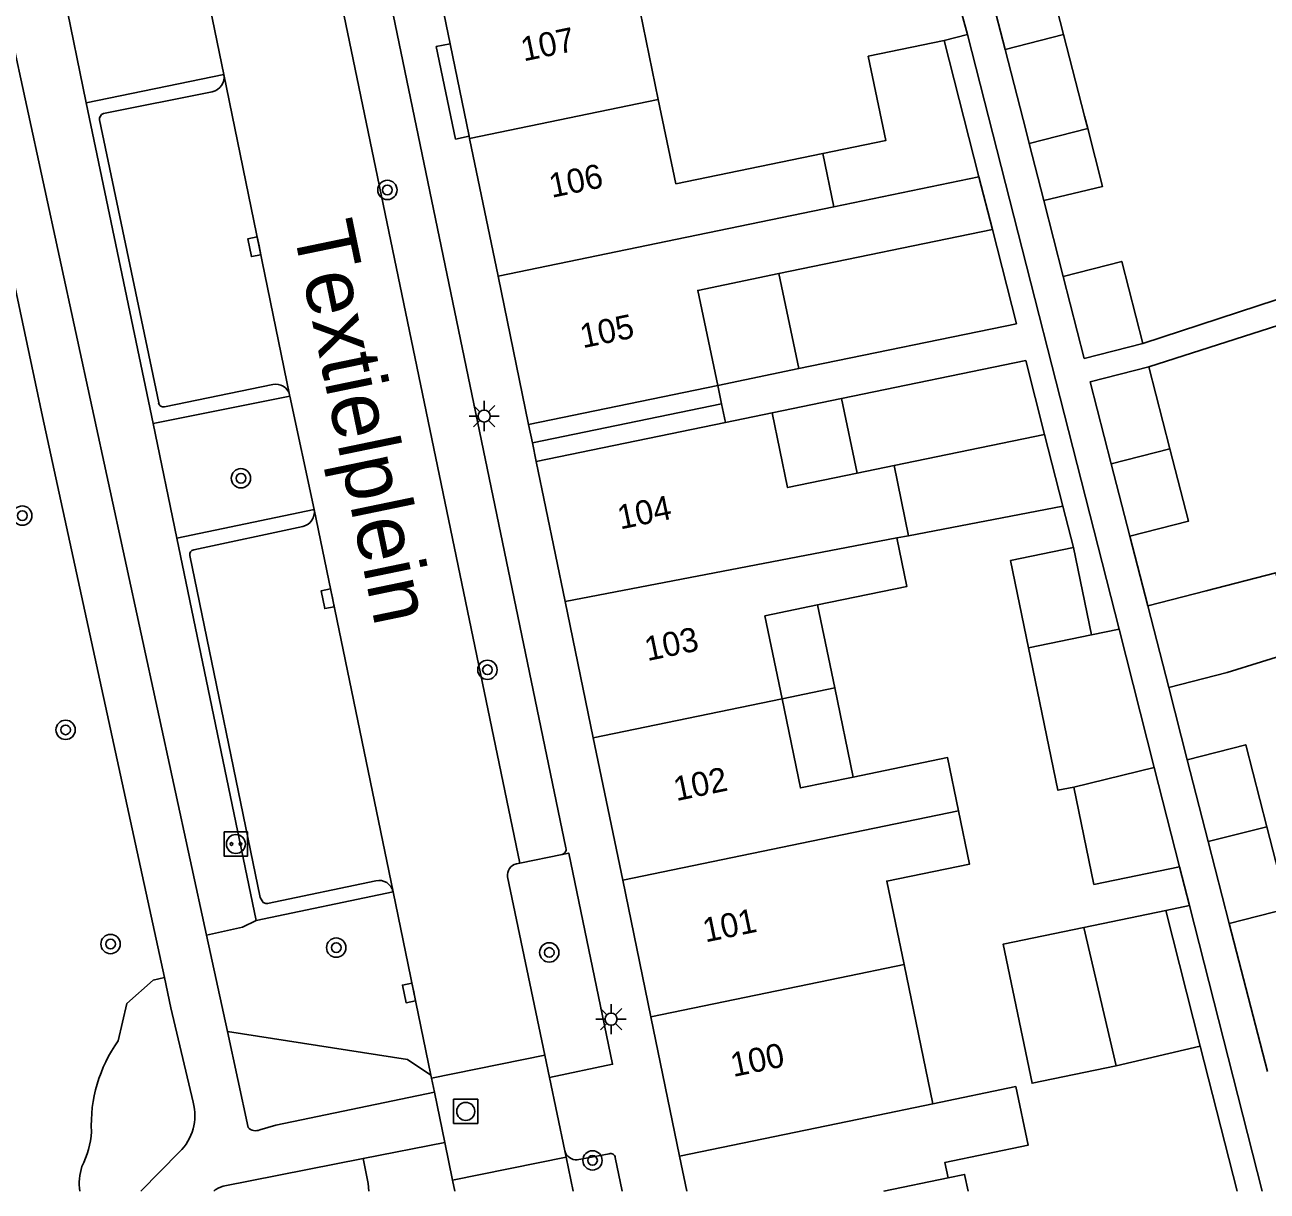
# Model space of a CAD drawing. Extents: x 132999 to 136000, y 398499 to 400501.
# Drawn here: x 133326.1 to 133377.5, y 398500 to 398548.3 of the extents above; entities that cross this region are included whole.
import ezdxf

# ---------------------------------------------------------------- set-up
doc = ezdxf.new("R2010")
doc.units = 0
for name, color, linetype in [('gg-afsc-erfafscheiding', 7, 'Continuous'), ('gg-anno-huisnummerreeks BGT', 7, 'Continuous'), ('gg-anno-openbare ruimte label', 7, 'Continuous'), ('gg-bbg-gedigitaliseerde bebouwing', 7, 'Continuous'), ('gg-bbg-gedigitaliseerde bijgebouw', 7, 'Continuous'), ('gg-bbg-hoofdgebouw', 7, 'Continuous'), ('gg-bbg-luifel en loopbrug', 7, 'Continuous'), ('gg-bbg-onder overbouw', 7, 'Continuous'), ('gg-bbg-pand overbouw', 7, 'Continuous'), ('gg-bbg-tussenscheiding', 7, 'Continuous'), ('gg-bbg-tussenscheiding niveau 01', 7, 'Continuous'), ('gg-knt-verharding', 7, 'Continuous'), ('gg-knt-verharding nz', 7, 'Continuous'), ('gt-grn-groengrens', 7, 'Continuous'), ('gt-symb-boom', 7, 'Continuous'), ('gt-symb-kolk', 7, 'Continuous'), ('gt-symb-laadpunt elektrisch vervoer', 7, 'Continuous'), ('gt-symb-lichtmast', 7, 'Continuous'), ('gt-symb-rioolschacht', 7, 'Continuous')]:
    doc.layers.add(name, color=color, linetype=linetype)

# ---------------------------------------------------------------- blocks, each defined once
blk = doc.blocks.new('gt0-BOOM')
at = {"layer": 'gt-symb-boom'}
for radius in [0.4, 0.2]:
    blk.add_circle((0, 0), radius, dxfattribs=at)
blk = doc.blocks.new('gt0-LMAST')
at = {"layer": 'gt-symb-lichtmast'}
for p, q in [((-0.005, 0.246), (-0.005, 0.621)), ((-0.182, 0.173), (-0.447, 0.438)), ((0.172, 0.173), (0.437, 0.438)), ((-0.255, -0.004), (-0.63, -0.004)), ((-0.182, -0.181), (-0.447, -0.446)), ((-0.005, -0.254), (-0.005, -0.629)), ((0.437, -0.446), (0.172, -0.181)), ((0.245, -0.004), (0.62, -0.004))]:
    blk.add_line(p, q, dxfattribs=at)
blk.add_circle((-0.005, -0.004), 0.25, dxfattribs=at)
blk = doc.blocks.new('gt0-KOLK')
at = {"layer": 'gt-symb-kolk'}
blk.add_lwpolyline([(0, 0), (0.375, 0), (0.375, 0.4), (-0.375, 0.4), (-0.375, 0), (0, 0)], dxfattribs=at)
blk = doc.blocks.new('gt0-LEV')
at = {"layer": 'gt-symb-laadpunt elektrisch vervoer'}
blk.add_lwpolyline([(-0.486, 0.501), (0.486, 0.501), (0.486, -0.499), (-0.486, -0.499)], close=True, dxfattribs=at)
for centre, radius in [((0, 0), 0.393), ((-0.186, 0), 0.0566), ((0.186, 0), 0.0566)]:
    blk.add_circle(centre, radius, dxfattribs=at)
blk = doc.blocks.new('gt0-RS')
at = {"layer": 'gt-symb-rioolschacht'}
blk.add_lwpolyline([(-0.5, -0.5), (0.5, -0.5), (0.5, 0.5), (-0.5, 0.5)], close=True, dxfattribs=at)
blk.add_circle((0, 0), 0.375, dxfattribs=at)

msp = doc.modelspace()

# ---------------------------------------------------------------- linework, layer by layer
at = {"layer": 'gg-afsc-erfafscheiding'}
for p, q in [((133362.02, 398559.272), (133365.133, 398547.875)), ((133364.167, 398547.629), (133365.133, 398547.875)), ((133365.133, 398547.875), (133371.404, 398523.26)), ((133368.29, 398541.009), (133369.097, 398537.861)), ((133382.979, 398538.564), (133372.388, 398535.091)), ((133383.297, 398537.543), (133372.637, 398534.122)), ((133369.074, 398528.357), (133369.512, 398526.638)), ((133371.853, 398527.11), (133372.591, 398524.233)), ((133373.46, 398520.842), (133374.227, 398517.859)), ((133373.907, 398513.428), (133374.317, 398511.817)), ((133373.336, 398511.615), (133374.317, 398511.817)), ((133374.317, 398511.817), (133377.324, 398500)), ((133375.967, 398511.079), (133377.548, 398504.946)), ((133374.765, 398506.006), (133376.293, 398500))]:
    msp.add_line(p, q, dxfattribs=at)
for points in [[(133358.149, 398534.046), (133367.153, 398535.904), (133366.161, 398539.802)], [(133359.921, 398532.809), (133367.541, 398534.381), (133368.321, 398531.317)]]:
    msp.add_lwpolyline(points, dxfattribs=at)
at = {"layer": 'gg-bbg-gedigitaliseerde bebouwing'}
for p, q in [((133352.328, 398545.185), (133351.174, 398550.773)), ((133353.051, 398541.69), (133352.328, 398545.185)), ((133353.051, 398541.69), (133359.147, 398542.949)), ((133359.147, 398542.949), (133359.602, 398540.745)), ((133359.602, 398540.745), (133365.605, 398541.984)), ((133365.605, 398541.984), (133366.161, 398539.802)), ((133366.161, 398539.802), (133357.327, 398537.979)), ((133355.114, 398531.817), (133357.043, 398532.215)), ((133360.56, 398529.714), (133362.089, 398530.03)), ((133362.687, 398527.131), (133362.202, 398527.038)), ((133363.693, 398503.614), (133362.503, 398509.379)), ((133363.693, 398503.614), (133367.135, 398504.325))]:
    msp.add_line(p, q, dxfattribs=at)
for points in [[(133357.327, 398537.979), (133353.967, 398537.285), (133354.789, 398533.353)], [(133357.043, 398532.215), (133357.682, 398529.12), (133360.56, 398529.714)], [(133358.927, 398524.263), (133362.617, 398525.024), (133362.202, 398527.038)], [(133357.453, 398520.38), (133356.744, 398523.812), (133358.927, 398524.263)], [(133357.453, 398520.38), (133358.216, 398516.69), (133360.399, 398517.14)], [(133360.399, 398517.14), (133364.308, 398517.947), (133364.763, 398515.744)], [(133362.503, 398509.379), (133361.79, 398512.833), (133365.218, 398513.54), (133364.763, 398515.744)], [(133367.135, 398504.325), (133367.636, 398501.9), (133364.193, 398501.19), (133364.325, 398500.554)], [(133361.669, 398500), (133361.668, 398500.006), (133364.325, 398500.554)]]:
    msp.add_lwpolyline(points, dxfattribs=at)
at = {"layer": 'gg-bbg-gedigitaliseerde bijgebouw'}
for p, q in [((133368.239, 398551.274), (133369.109, 398547.883)), ((133365.817, 398550.653), (133366.687, 398547.262)), ((133369.109, 398547.883), (133369.978, 398544.493)), ((133366.687, 398547.262), (133367.556, 398543.872)), ((133370.109, 398543.981), (133369.978, 398544.493)), ((133367.556, 398543.872), (133367.687, 398543.36)), ((133367.687, 398543.36), (133370.109, 398543.981)), ((133373.506, 398530.731), (133372.637, 398534.122)), ((133362.089, 398530.03), (133368.321, 398531.317)), ((133368.321, 398531.317), (133369.074, 398528.357)), ((133371.084, 398530.11), (133373.506, 398530.731)), ((133369.074, 398528.357), (133362.687, 398527.131)), ((133369.512, 398526.638), (133370.258, 398523.023)), ((133372.591, 398524.233), (133375.013, 398524.854)), ((133372.591, 398524.233), (133373.46, 398520.842)), ((133371.404, 398523.26), (133370.258, 398523.023)), ((133372.862, 398517.53), (133371.404, 398523.26)), ((133375.882, 398521.463), (133373.46, 398520.842)), ((133374.227, 398517.859), (133375.097, 398514.469)), ((133373.907, 398513.428), (133372.862, 398517.53)), ((133375.097, 398514.469), (133375.967, 398511.079)), ((133369.943, 398510.915), (133373.336, 398511.615)), ((133374.765, 398506.006), (133373.336, 398511.615)), ((133371.291, 398505.188), (133369.943, 398510.915)), ((133374.765, 398506.006), (133371.291, 398505.188))]:
    msp.add_line(p, q, dxfattribs=at)
for points in [[(133372.388, 398535.091), (133371.519, 398538.482), (133369.097, 398537.861)], [(133369.097, 398537.861), (133369.966, 398534.47), (133372.388, 398535.091)], [(133372.637, 398534.122), (133370.215, 398533.501), (133371.084, 398530.11)], [(133367.659, 398522.487), (133366.913, 398526.101), (133369.512, 398526.638)], [(133375.882, 398521.463), (133378.728, 398522.348), (133377.896, 398525.593), (133375.013, 398524.854)], [(133367.659, 398522.487), (133368.876, 398516.592), (133369.535, 398516.728)], [(133374.227, 398517.859), (133376.649, 398518.481), (133377.523, 398515.074)], [(133369.535, 398516.728), (133370.367, 398512.698), (133373.907, 398513.428)], [(133377.523, 398515.074), (133378.389, 398511.699), (133375.967, 398511.079)]]:
    msp.add_lwpolyline(points, dxfattribs=at)
at = {"layer": 'gg-bbg-hoofdgebouw'}
for p, q in [((133343.71, 398547.495), (133343.366, 398549.161)), ((133344.5, 398543.667), (133343.71, 398547.495)), ((133344.519, 398543.573), (133344.5, 398543.667)), ((133345.695, 398537.875), (133344.519, 398543.573)), ((133346.962, 398531.738), (133345.695, 398537.875)), ((133348.476, 398524.403), (133347.279, 398530.2)), ((133349.639, 398518.767), (133348.476, 398524.403)), ((133350.856, 398512.873), (133349.639, 398518.767)), ((133352.024, 398507.216), (133350.856, 398512.873)), ((133353.213, 398501.451), (133352.024, 398507.216)), ((133353.213, 398501.451), (133353.513, 398500))]:
    msp.add_line(p, q, dxfattribs=at)
at = {"layer": 'gg-bbg-luifel en loopbrug'}
for p, q in [((133365.605, 398541.984), (133364.167, 398547.629)), ((133367.687, 398543.36), (133368.29, 398541.009)), ((133357.327, 398537.979), (133358.149, 398534.046)), ((133354.789, 398533.353), (133358.149, 398534.046)), ((133357.043, 398532.215), (133359.921, 398532.809)), ((133360.56, 398529.714), (133359.921, 398532.809)), ((133371.084, 398530.11), (133371.853, 398527.11)), ((133358.927, 398524.263), (133359.636, 398520.831)), ((133359.636, 398520.831), (133357.453, 398520.38)), ((133360.399, 398517.14), (133359.636, 398520.831))]:
    msp.add_line(p, q, dxfattribs=at)
for points in [[(133364.167, 398547.629), (133361.022, 398546.98), (133361.744, 398543.485), (133359.147, 398542.949)], [(133368.29, 398541.009), (133370.723, 398541.589), (133370.109, 398543.981)], [(133371.853, 398527.11), (133374.275, 398527.731), (133373.506, 398530.731)], [(133369.943, 398510.915), (133366.61, 398510.227), (133367.806, 398504.464), (133371.291, 398505.188)], [(133364.325, 398500.554), (133365.009, 398500.695), (133365.155, 398500)]]:
    msp.add_lwpolyline(points, dxfattribs=at)
at = {"layer": 'gg-bbg-onder overbouw'}
for p, q in [((133346.962, 398531.738), (133354.789, 398533.353)), ((133347.279, 398530.2), (133355.114, 398531.817))]:
    msp.add_line(p, q, dxfattribs=at)
at = {"layer": 'gg-bbg-pand overbouw'}
for p, q in [((133354.789, 398533.353), (133354.952, 398532.585)), ((133354.952, 398532.585), (133355.114, 398531.817)), ((133346.962, 398531.738), (133347.12, 398530.969)), ((133347.12, 398530.969), (133347.279, 398530.2))]:
    msp.add_line(p, q, dxfattribs=at)
at = {"layer": 'gg-bbg-tussenscheiding'}
for p, q in [((133369.109, 398547.883), (133366.687, 398547.262)), ((133352.328, 398545.185), (133344.519, 398543.573)), ((133353.506, 398539.487), (133359.602, 398540.745)), ((133353.506, 398539.487), (133345.695, 398537.875)), ((133362.089, 398530.03), (133362.687, 398527.131)), ((133362.202, 398527.038), (133348.476, 398524.403)), ((133370.258, 398523.023), (133367.659, 398522.487)), ((133357.453, 398520.38), (133349.639, 398518.767)), ((133369.535, 398516.728), (133372.862, 398517.53)), ((133358.671, 398514.486), (133364.763, 398515.744)), ((133377.523, 398515.074), (133375.097, 398514.469)), ((133358.671, 398514.486), (133350.856, 398512.873)), ((133359.84, 398508.829), (133362.503, 398509.379)), ((133359.84, 398508.829), (133352.024, 398507.216)), ((133361.031, 398503.065), (133363.693, 398503.614)), ((133361.031, 398503.065), (133353.213, 398501.451))]:
    msp.add_line(p, q, dxfattribs=at)
at = {"layer": 'gg-bbg-tussenscheiding niveau 01'}
msp.add_line((133347.12, 398530.969), (133354.952, 398532.585), dxfattribs=at)
at = {"layer": 'gg-knt-verharding'}
for p, q in [((133338.96, 398560.244), (133348.505, 398514.204)), ((133333.051, 398552.517), (133334.344, 398546.217)), ((133334.344, 398546.217), (133328.647, 398545.052)), ((133328.647, 398545.052), (133331.421, 398531.773)), ((133333.867, 398545.506), (133329.358, 398544.604)), ((133329.198, 398544.347), (133331.647, 398532.628)), ((133331.887, 398532.467), (133336.373, 398533.384)), ((133331.421, 398531.773), (133337.08, 398532.91)), ((133337.069, 398532.966), (133337.08, 398532.91)), ((133337.08, 398532.91), (133338.084, 398528.209)), ((133338.084, 398528.209), (133332.394, 398527.031)), ((133332.394, 398527.031), (133335.682, 398511.208)), ((133337.618, 398527.509), (133333.1, 398526.548)), ((133348.344, 398513.939), (133346.599, 398513.58)), ((133346.599, 398513.58), (133346.454, 398513.55)), ((133346.094, 398513.016), (133347.636, 398505.622)), ((133335.682, 398511.208), (133341.348, 398512.396)), ((133341.348, 398512.396), (133342.917, 398504.801)), ((133333.628, 398510.589), (133334.493, 398506.602)), ((133334.493, 398506.602), (133335.35, 398502.638)), ((133342.944, 398504.67), (133347.636, 398505.622)), ((133347.636, 398505.622), (133347.826, 398504.711)), ((133342.917, 398504.801), (133342.944, 398504.67)), ((133342.944, 398504.67), (133343.063, 398504.093)), ((133347.826, 398504.711), (133348.461, 398501.663)), ((133343.063, 398504.093), (133343.492, 398502.019)), ((133343.492, 398502.019), (133340.11, 398501.351)), ((133343.492, 398502.019), (133343.815, 398500.454)), ((133330.914, 398500), (133332.512, 398501.622)), ((133348.523, 398501.408), (133343.815, 398500.454)), ((133348.461, 398501.663), (133348.523, 398501.408)), ((133348.975, 398501.301), (133350.294, 398501.54)), ((133350.548, 398501.387), (133350.833, 398500)), ((133343.815, 398500.454), (133343.909, 398500))]:
    msp.add_line(p, q, dxfattribs=at)
for points in [[(133333.628, 398510.589), (133322.789, 398560.498), (133330.81, 398562.273)], [(133343.71, 398547.495), (133343.139, 398547.377), (133343.936, 398543.551), (133344.5, 398543.667)], [(133331.886, 398508.839), (133326.84, 398532.067), (133324.915, 398541.046)], [(133332.937, 398526.307), (133335.848, 398512.151), (133335.973, 398511.953), (133336.08, 398511.904), (133336.154, 398511.906), (133340.642, 398512.851)], [(133347.826, 398504.711), (133350.439, 398505.256), (133348.62, 398513.996), (133348.344, 398513.939)], [(133333.071, 398503.677), (133332.157, 398507.592), (133331.886, 398508.839)], [(133343.063, 398504.093), (133336.492, 398502.727), (133335.833, 398502.539)], [(133333.933, 398500), (133333.983, 398500.05), (133334.141, 398500.14), (133334.314, 398500.208), (133340.11, 398501.351)]]:
    msp.add_lwpolyline(points, dxfattribs=at)
for centre, radius, start, end in [((133333.737, 398546.109), 0.616, 282.1501, 10.1357), ((133329.446, 398544.371), 0.249, 110.7406, 185.4493), ((133336.507, 398532.819), 0.581, 14.6517, 103.3724), ((133331.843, 398532.661), 0.199, 189.5214, 282.7686), ((133337.469, 398528.114), 0.623, 283.8829, 8.8126), ((133333.143, 398526.343), 0.209, 101.816, 190.0392), ((133348.295, 398514.15), 0.217, 283.0094, 14.4293), ((133346.552, 398513.095), 0.465, 102.1887, 189.839), ((133340.769, 398512.273), 0.592, 12.0323, 102.3661), ((133331.037, 398503.127), 2.107, 314.4322, 15.133), ((133335.661, 398502.925), 0.423, 222.7804, 294.0528), ((133348.93, 398501.783), 0.484, 194.3585, 275.329), ((133350.369, 398501.377), 0.179, 3.1606, 114.713)]:
    msp.add_arc(centre, radius, start, end, dxfattribs=at)
at = {"layer": 'gg-knt-verharding nz'}
for p, q in [((133336.955, 398560.038), (133346.599, 398513.58)), ((133334.344, 398546.217), (133337.069, 398532.966)), ((133338.084, 398528.209), (133341.348, 398512.396)), ((133348.523, 398501.408), (133348.811, 398500))]:
    msp.add_line(p, q, dxfattribs=at)
at = {"layer": 'gt-grn-groengrens'}
for p, q in [((133327.363, 398551.302), (133328.647, 398545.052)), ((133331.421, 398531.773), (133332.394, 398527.031))]:
    msp.add_line(p, q, dxfattribs=at)
for points in [[(133333.628, 398510.589), (133335.122, 398510.927), (133335.682, 398511.208)], [(133329.973, 398506.219), (133330.331, 398507.761), (133331.42, 398508.738), (133331.886, 398508.839)], [(133342.917, 398504.801), (133341.95, 398505.447), (133334.493, 398506.602)], [(133340.11, 398501.351), (133340.314, 398500.315), (133340.352, 398500)]]:
    msp.add_lwpolyline(points, dxfattribs=at)
for centre, radius, start, end in [((133334.815, 398502.749), 5.957, 144.3699, 182.8082), ((133324.955, 398502.756), 3.921, 333.7472, 355.621), ((133330.689, 398500.307), 2.329, 162.1291, 187.5831)]:
    msp.add_arc(centre, radius, start, end, dxfattribs=at)

# ---------------------------------------------------------------- block references
at = {"layer": 'gt-symb-boom'}
for p in [(133341.116, 398541.442), (133335.052, 398529.506), (133326.002, 398527.962), (133345.258, 398521.579), (133327.793, 398519.094), (133329.655, 398510.23), (133338.997, 398510.079), (133347.816, 398509.88), (133349.607, 398501.273)]:
    msp.add_blockref('gt0-BOOM', p, dxfattribs=at)
at = {"layer": 'gt-symb-kolk'}
for p, rotation in [((133335.801, 398539.129), 101.62014968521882), ((133338.837, 398524.559), 101.66129997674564), ((133342.205, 398508.245), 101.67710663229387)]:
    msp.add_blockref('gt0-KOLK', p, dxfattribs=dict(at, rotation=rotation))
at = {"layer": 'gt-symb-laadpunt elektrisch vervoer'}
msp.add_blockref('gt0-LEV', (133334.844, 398514.369), dxfattribs=at)
at = {"layer": 'gt-symb-lichtmast'}
for p in [(133345.128, 398532.086), (133350.38, 398507.121)]:
    msp.add_blockref('gt0-LMAST', p, dxfattribs=at)
at = {"layer": 'gt-symb-rioolschacht'}
msp.add_blockref('gt0-RS', (133344.359, 398503.301), dxfattribs=at)

# ---------------------------------------------------------------- texts
at = {"layer": 'gg-anno-huisnummerreeks BGT'}
for s, p in [('107', (133346.756, 398546.76)), ('106', (133347.921, 398541.113)), ('105', (133349.206, 398534.888)), ('104', (133350.755, 398527.385)), ('103', (133351.879, 398521.938)), ('102', (133353.075, 398516.142)), ('101', (133354.283, 398510.293)), ('100', (133355.433, 398504.722))]:
    msp.add_text(s, height=1, rotation=11.7, dxfattribs=at).set_placement(p)
at = {"layer": 'gg-anno-openbare ruimte label'}
msp.add_text('Textielplein', height=2.5, rotation=281.7, dxfattribs=at).set_placement((133337.192, 398539.877))

doc.saveas('drawing.dxf')
